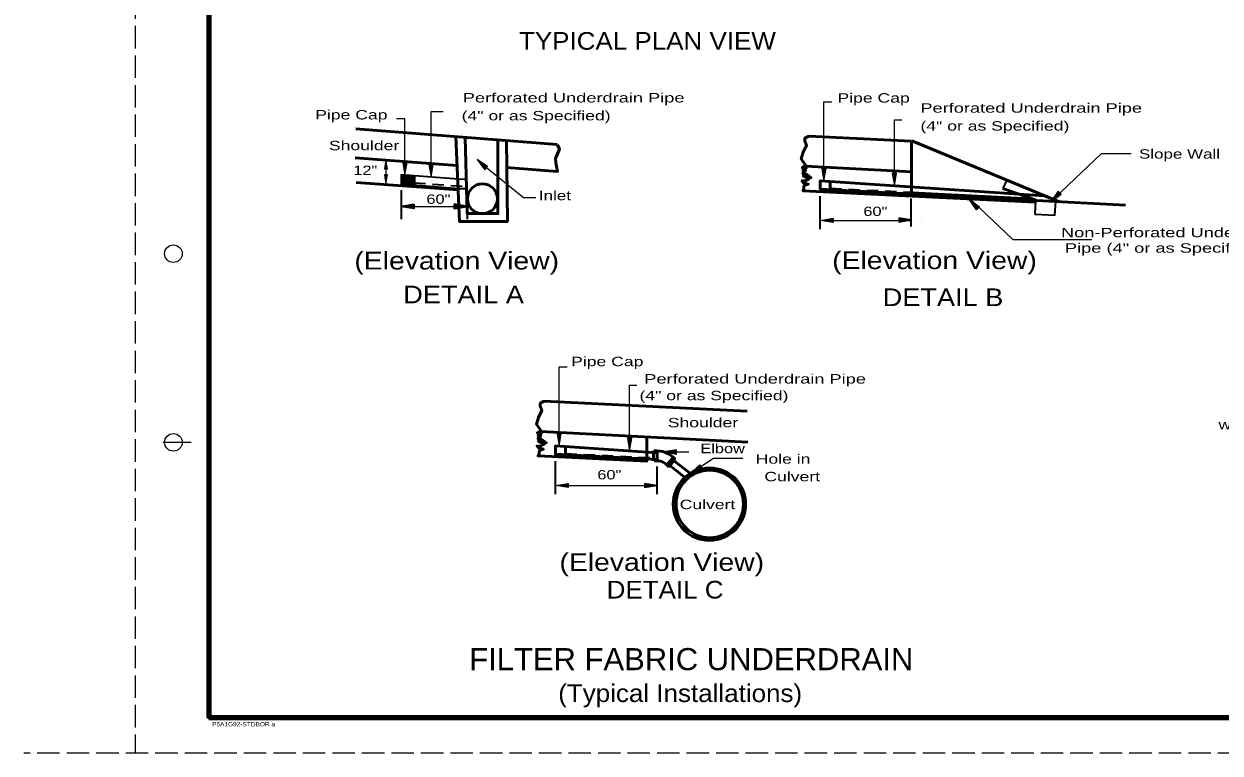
# Model space of a CAD drawing. Extents: x 36 to 71.3, y 0.3 to 22.3.
# Drawn here: x 35.97 to 52.91, y 0.32 to 10.65 of the extents above; entities that cross this region are included whole.
import ezdxf

# ---------------------------------------------------------------- set-up
doc = ezdxf.new("R2010")
doc.units = 0
doc.header["$LTSCALE"] = 0.053
doc.header["$PDMODE"] = 32
doc.header["$PDSIZE"] = 0.0265
doc.linetypes.add('LONG_DASHED', pattern=[7.5, 6, -1.5])
doc.linetypes.add('MEDIUM_DASHED', pattern=[4.5, 3, -1.5])
for name, color, linetype, lineweight in [('1', 7, 'Continuous', 13), ('2', 7, 'Continuous', 13), ('3', 7, 'MEDIUM_DASHED', 53), ('4', 7, 'Continuous', 13)]:
    doc.layers.add(name, color=color, linetype=linetype, lineweight=lineweight)

msp = doc.modelspace()

# ---------------------------------------------------------------- hatches: boundary and pattern name
at = {"layer": '1'}
for points in [[(41.49425, 8.09608), (41.49425, 8.03608), (41.31425, 8.06608), (41.31425, 8.06608)], [(42.068, 8.09608), (42.068, 8.03608), (42.248, 8.06608), (42.248, 8.06608)], [(47.43092, 7.89775), (47.43092, 7.83775), (47.25092, 7.86775), (47.25092, 7.86775)], [(48.36508, 7.9035), (48.36508, 7.8435), (48.54508, 7.8735), (48.54508, 7.8735)], [(43.68133, 4.14325), (43.68133, 4.08325), (43.50133, 4.11325), (43.50133, 4.11325)], [(44.76017, 4.14325), (44.76017, 4.08325), (44.94017, 4.11325), (44.94017, 4.11325)]]:
    msp.add_hatch(color=256, dxfattribs=at).paths.add_polyline_path(points)
at = {"layer": '2'}
for points in [[(41.07933, 8.59492), (41.12133, 8.59492), (41.10033, 8.72092), (41.10033, 8.72092)], [(41.3985, 8.6875), (41.33842, 8.6875), (41.3685, 8.5075), (41.3685, 8.5075)], [(41.76967, 8.66058), (41.70967, 8.66058), (41.73967, 8.48058), (41.73967, 8.48058)], [(42.49842, 8.58508), (42.54008, 8.62817), (42.38983, 8.73167), (42.38983, 8.73167)], [(41.12067, 8.51042), (41.07858, 8.51042), (41.09967, 8.38442), (41.09967, 8.38442)], [(47.3325, 8.60425), (47.2725, 8.60425), (47.3025, 8.42425), (47.3025, 8.42425)], [(48.33058, 8.53792), (48.27058, 8.53792), (48.30058, 8.35792), (48.30058, 8.35792)], [(49.50558, 8.05942), (49.46217, 8.01792), (49.35958, 8.16892), (49.35958, 8.16892)], [(50.66292, 8.23942), (50.6195, 8.28092), (50.51692, 8.12992), (50.51692, 8.12992)], [(43.58292, 4.84975), (43.52292, 4.84975), (43.55292, 4.66975), (43.55292, 4.66975)], [(44.581, 4.78342), (44.521, 4.78342), (44.551, 4.60342), (44.551, 4.60342)], [(45.21667, 4.5575), (45.21667, 4.6175), (45.03667, 4.5875), (45.03667, 4.5875)], [(45.57683, 4.35783), (45.54383, 4.408), (45.40992, 4.28408), (45.40992, 4.28408)]]:
    msp.add_hatch(color=256, dxfattribs=at).paths.add_polyline_path(points)

# ---------------------------------------------------------------- linework, layer by layer
at = {"layer": '1', "linetype": 'LONG_DASHED', "lineweight": 25}
for p, q in [((37.54825, 22.32408), (37.54825, 0.32408)), ((71.17325, 0.32408), (35.97325, 0.32408))]:
    msp.add_line(p, q, dxfattribs=at)
at = {"layer": '1', "lineweight": 158}
msp.add_line((38.58992, 21.82408), (38.58992, 0.82408), dxfattribs=at)
at = {"layer": '1', "lineweight": 53}
for p, q in [((43.52525, 8.94167), (40.67283, 9.16183)), ((48.54408, 8.98942), (47.09092, 9.0615)), ((48.54408, 8.21133), (48.54408, 8.98433)), ((50.62542, 8.13375), (48.54675, 8.99183)), ((42.10342, 8.64642), (40.66417, 8.75333)), ((48.55392, 8.55517), (47.04233, 8.63392)), ((42.12075, 8.3015), (40.678, 8.40458)), ((47.393, 8.303), (47.393, 8.41625)), ((50.30617, 8.15142), (49.83617, 8.31967)), ((46.22508, 4.72667), (43.29275, 4.87942)), ((43.64342, 4.5485), (43.64342, 4.66175)), ((44.89, 4.60192), (44.89, 4.4645)), ((45.1035, 4.37542), (45.1955, 4.48617))]:
    msp.add_line(p, q, dxfattribs=at)
at = {"layer": '1'}
for p, q in [((41.34433, 8.50792), (41.3145, 8.48583)), ((41.3145, 8.42708), (41.40508, 8.503)), ((41.315, 8.46725), (41.36442, 8.50492)), ((41.315, 8.49708), (41.41583, 8.38008)), ((41.31542, 8.39425), (41.44475, 8.5005)), ((41.31592, 8.44808), (41.38792, 8.504)), ((41.31642, 8.41042), (41.42267, 8.502)), ((41.31642, 8.46967), (41.39375, 8.38058)), ((41.32275, 8.38542), (41.46725, 8.49908)), ((41.32725, 8.50842), (41.44475, 8.37667)), ((41.34342, 8.38542), (41.48833, 8.49758)), ((41.35617, 8.50592), (41.46925, 8.37517)), ((41.36933, 8.3835), (41.49867, 8.48533)), ((41.37958, 8.50492), (41.49417, 8.37317)), ((41.40017, 8.503), (41.50017, 8.383)), ((41.41833, 8.502), (41.50158, 8.406)), ((41.44675, 8.49958), (41.50058, 8.43592)), ((41.47317, 8.49858), (41.50208, 8.46325)), ((41.31592, 8.44958), (41.37425, 8.383)), ((41.31592, 8.42858), (41.35708, 8.38492)), ((41.31592, 8.41042), (41.33742, 8.38592)), ((41.39725, 8.38058), (41.49967, 8.46575)), ((41.41783, 8.37808), (41.50017, 8.44717)), ((41.43833, 8.37767), (41.50058, 8.42758)), ((41.46192, 8.37517), (41.50058, 8.406)), ((41.48933, 8.37275), (41.50017, 8.38542)), ((38.33992, 4.72408), (37.93992, 4.72408))]:
    msp.add_line(p, q, dxfattribs=at)
at = {"layer": '1', "lineweight": 35}
for p, q in [((41.50267, 8.48858), (41.50267, 8.37658)), ((49.88608, 8.43317), (49.83617, 8.31967)), ((41.31425, 8.29667), (41.31425, 7.88608)), ((47.25092, 7.74325), (47.25092, 8.212)), ((48.53658, 7.78233), (48.53658, 8.17633)), ((42.248, 8.00383), (42.248, 7.88608)), ((43.50133, 3.98875), (43.50133, 4.4575)), ((44.94017, 3.98875), (44.94017, 4.38275))]:
    msp.add_line(p, q, dxfattribs=at)
at = {"layer": '1', "lineweight": 25}
for p, q in [((41.49425, 8.06608), (42.068, 8.06608)), ((47.43092, 7.86775), (48.53983, 7.86775)), ((43.68133, 4.11325), (44.76017, 4.11325))]:
    msp.add_line(p, q, dxfattribs=at)
at = {"layer": '1', "lineweight": 158}
msp.add_lwpolyline([(71.08992, 21.82408), (71.08992, 0.82408), (38.58992, 0.82408)], dxfattribs=at)
at = {"layer": '1', "lineweight": 53}
for points in [[(42.0895, 9.04983), (42.13983, 7.85225), (42.82042, 7.85225), (42.80825, 9.00017)], [(42.21967, 9.04092), (42.25092, 7.96425), (42.68675, 7.96425), (42.68675, 9.01417)], [(47.09092, 9.0615), (47.03367, 9.03225), (47.03367, 8.99408), (47.05625, 8.92792), (47.00933, 8.83242), (46.98158, 8.73825), (47.04233, 8.64792), (46.9955, 8.61483), (47.05275, 8.60975), (47.00417, 8.57667), (47.04233, 8.57667), (47.00417, 8.53842), (47.00417, 8.5295), (47.04233, 8.5295), (47.07183, 8.51042), (47.11875, 8.47225), (47.00933, 8.49642), (47.09092, 8.45317), (47.07533, 8.44808), (47.03883, 8.42517), (46.99025, 8.42517), (47.00933, 8.401), (47.0805, 8.38192), (47.02325, 8.36283), (47.01975, 8.34375), (47.01975, 8.31575), (47.00417, 8.2865), (50.29583, 8.12583)], [(43.53042, 8.93783), (43.5565, 8.87417), (43.50267, 8.74442), (43.50792, 8.682), (43.53042, 8.56108), (42.80825, 8.61458)], [(51.57533, 8.08125), (47.25067, 8.31067), (47.25067, 8.42775), (50.42208, 8.21692)], [(46.21467, 5.1645), (43.34133, 5.307), (43.28408, 5.27775), (43.28408, 5.23958), (43.30667, 5.17342), (43.25975, 5.07792), (43.232, 4.98375), (43.29275, 4.89342), (43.24592, 4.86033), (43.30317, 4.85525), (43.25458, 4.82217), (43.29275, 4.82217), (43.25458, 4.78392), (43.25458, 4.775), (43.29275, 4.775), (43.32225, 4.75592), (43.36917, 4.71775), (43.25975, 4.74192), (43.34133, 4.69867), (43.32575, 4.69358), (43.28925, 4.67067), (43.24067, 4.67067), (43.25975, 4.6465), (43.33092, 4.62742), (43.27367, 4.60833), (43.27017, 4.58925), (43.27017, 4.56125), (43.25458, 4.532), (44.7945, 4.45683), (44.7945, 4.803)], [(44.94208, 4.58033), (44.94208, 4.47975), (43.50108, 4.55617), (43.50108, 4.67325), (44.93683, 4.57775)], [(45.43508, 4.26467), (45.14692, 4.48617), (45.08967, 4.42), (45.37608, 4.19467)]]:
    msp.add_lwpolyline(points, dxfattribs=at)
at = {"layer": '1', "lineweight": 35}
msp.add_lwpolyline([(42.12075, 8.45292), (41.31342, 8.5115), (41.31342, 8.3855), (42.12592, 8.31933)], dxfattribs=at)
for points in [[(50.28683, 7.95717), (50.57458, 7.94217), (50.58483, 8.13425), (50.29675, 8.14942)], [(41.49425, 8.09608), (41.49425, 8.03608), (41.31425, 8.06608), (41.31425, 8.06608)], [(42.068, 8.09608), (42.068, 8.03608), (42.248, 8.06608), (42.248, 8.06608)]]:
    msp.add_lwpolyline(points, close=True, dxfattribs=at)
at = {"layer": '1'}
for points in [[(47.43092, 7.89775), (47.43092, 7.83775), (47.25092, 7.86775), (47.25092, 7.86775)], [(48.36508, 7.9035), (48.36508, 7.8435), (48.54508, 7.8735), (48.54508, 7.8735)], [(43.68133, 4.14325), (43.68133, 4.08325), (43.50133, 4.11325), (43.50133, 4.11325)], [(44.76017, 4.14325), (44.76017, 4.08325), (44.94017, 4.11325), (44.94017, 4.11325)]]:
    msp.add_lwpolyline(points, close=True, dxfattribs=at)
at = {"layer": '1', "lineweight": 53}
for centre, radius in [((42.46708, 8.173), 0.21258), ((45.68075, 3.84858), 0.51289), ((45.68508, 3.85108), 0.47725)]:
    msp.add_circle(centre, radius, dxfattribs=at)
at = {"layer": '1'}
for centre in [(38.08992, 7.39575), (38.08992, 4.72408)]:
    msp.add_circle(centre, 0.125, dxfattribs=at)
at = {"layer": '1', "lineweight": 53}
for centre, radius, start, end in [((44.92942, 4.24708), 0.35686, 41.78259, 96.06632), ((44.93925, 4.2665), 0.19717, 32.66104, 101.88244)]:
    msp.add_arc(centre, radius, start, end, dxfattribs=at)
at = {"layer": '1'}
msp.add_point((38.58992, 0.82408), dxfattribs=at)
at = {"layer": '2', "lineweight": 25}
for p, q in [((41.10033, 8.72092), (41.10033, 8.37725)), ((49.97683, 7.596), (49.31467, 8.22283)), ((49.97683, 7.596), (51.0975, 7.596)), ((45.21667, 4.5875), (45.38892, 4.5875))]:
    msp.add_line(p, q, dxfattribs=at)
for points in [[(47.3025, 8.60425), (47.3025, 9.54808), (47.41417, 9.54808)], [(41.73967, 8.66058), (41.73967, 9.40767), (41.9115, 9.40767)], [(41.3685, 8.6875), (41.3685, 9.30583), (41.24817, 9.30583)], [(48.30058, 8.53792), (48.30058, 9.29058), (48.40433, 9.29058)], [(50.57092, 8.18633), (51.23308, 8.81317), (51.65125, 8.81317)], [(42.475, 8.65425), (43.04942, 8.18975), (43.22125, 8.18975)], [(43.55292, 4.84975), (43.55292, 5.79358), (43.66458, 5.79358)], [(44.551, 4.78342), (44.551, 5.53608), (44.65475, 5.53608)], [(45.56033, 4.38292), (45.7365, 4.49875), (46.15467, 4.49875)]]:
    msp.add_lwpolyline(points, dxfattribs=at)
at = {"layer": '2'}
for points in [[(41.07933, 8.59492), (41.12133, 8.59492), (41.10033, 8.72092), (41.10033, 8.72092)], [(41.3985, 8.6875), (41.33842, 8.6875), (41.3685, 8.5075), (41.3685, 8.5075)], [(41.76967, 8.66058), (41.70967, 8.66058), (41.73967, 8.48058), (41.73967, 8.48058)], [(42.49842, 8.58508), (42.54008, 8.62817), (42.38983, 8.73167), (42.38983, 8.73167)], [(41.12067, 8.51042), (41.07858, 8.51042), (41.09967, 8.38442), (41.09967, 8.38442)], [(47.3325, 8.60425), (47.2725, 8.60425), (47.3025, 8.42425), (47.3025, 8.42425)], [(48.33058, 8.53792), (48.27058, 8.53792), (48.30058, 8.35792), (48.30058, 8.35792)], [(49.50558, 8.05942), (49.46217, 8.01792), (49.35958, 8.16892), (49.35958, 8.16892)], [(50.66292, 8.23942), (50.6195, 8.28092), (50.51692, 8.12992), (50.51692, 8.12992)], [(43.58292, 4.84975), (43.52292, 4.84975), (43.55292, 4.66975), (43.55292, 4.66975)], [(44.581, 4.78342), (44.521, 4.78342), (44.551, 4.60342), (44.551, 4.60342)], [(45.21667, 4.5575), (45.21667, 4.6175), (45.03667, 4.5875), (45.03667, 4.5875)], [(45.57683, 4.35783), (45.54383, 4.408), (45.40992, 4.28408), (45.40992, 4.28408)]]:
    msp.add_lwpolyline(points, close=True, dxfattribs=at)
at = {"layer": '3', "lineweight": 35}
for p, q in [((41.50267, 8.3995), (42.23358, 8.34608)), ((42.23883, 8.444), (42.12075, 8.45292)), ((42.12592, 8.31933), (42.22842, 8.31933))]:
    msp.add_line(p, q, dxfattribs=at)
at = {"layer": '3'}
for p, q in [((47.393, 8.31192), (48.54742, 8.25558)), ((43.64342, 4.55742), (44.94033, 4.49375))]:
    msp.add_line(p, q, dxfattribs=at)
at = {"layer": '3', "linetype": 'Continuous'}
msp.add_line((48.54742, 8.2555), (50.23467, 8.17317), dxfattribs=at)
at = {"layer": '4', "lineweight": 35}
for p, q in [((41.31425, 8.35917), (41.31433, 8.35917)), ((42.248, 8.06633), (42.24808, 8.06633)), ((42.248, 8.06608), (42.24808, 8.06608))]:
    msp.add_line(p, q, dxfattribs=at)
at = {"layer": '4'}
for p, q in [((47.25092, 7.86775), (47.251, 7.86775)), ((48.68975, 7.86775), (48.68983, 7.86775)), ((48.68975, 7.836), (48.68983, 7.836)), ((43.50133, 4.11325), (43.50142, 4.11325)), ((44.94017, 4.11325), (44.94025, 4.11325)), ((44.94017, 4.0815), (44.94025, 4.0815))]:
    msp.add_line(p, q, dxfattribs=at)

# ---------------------------------------------------------------- texts
at = {"layer": '1', "width": 1.15}
msp.add_text('P5A1G92-STDBOR a', height=0.06, dxfattribs=at).set_placement((38.63792, 0.70308))
at = {"layer": '2'}
for s, height, width, p in [('TYPICAL PLAN VIEW', 0.25, 1.1, (42.98425, 10.28367)), ('Perforated Underdrain Pipe', 0.133, 1.45, (42.18883, 9.53733)), ('Pipe Cap', 0.133, 1.4, (47.49392, 9.535)), ('Perforated Underdrain Pipe', 0.133, 1.45, (48.66833, 9.39217)), ('Pipe Cap', 0.133, 1.4, (40.09792, 9.29692)), ('(4" or as Specified)', 0.133, 1.4, (42.1725, 9.28375)), ('(4" or as Specified)', 0.133, 1.4, (48.66917, 9.1385)), ('Shoulder', 0.133, 1.4, (40.29225, 8.86108)), ('Slope Wall', 0.133, 1.35, (51.76425, 8.74133)), ('12"', 0.133, 1.3, (40.63767, 8.50958)), ('60"', 0.133, 1.3, (41.67308, 8.102)), ('Inlet', 0.133, 1.35, (43.26633, 8.15283)), ('60"', 0.133, 1.3, (47.861, 7.92883)), (' Non-Perforated Underdrain', 0.133, 1.45, (50.58817, 7.62842)), ('Pipe (4" or as Specified)', 0.133, 1.45, (50.71592, 7.40958)), ('(Elevation View)', 0.25, 1.2, (40.653, 7.172)), ('(Elevation View)', 0.25, 1.2, (47.41942, 7.17733)), ('DETAIL A', 0.25, 1.15, (41.34467, 6.69242)), ('DETAIL B', 0.25, 1.15, (48.13433, 6.65358)), ('Pipe Cap', 0.133, 1.4, (43.72217, 5.80267)), ('Perforated Underdrain Pipe', 0.133, 1.45, (44.7585, 5.557)), ('(4" or as Specified)', 0.133, 1.4, (44.69092, 5.32058)), ('Shoulder', 0.133, 1.4, (45.09117, 4.937)), ('when placed at', 0.133, 1.4, (52.88983, 4.908)), ('Elbow', 0.133, 1.3, (45.55333, 4.57092)), ('Hole in', 0.133, 1.4, (46.33642, 4.42183)), ('60"', 0.133, 1.3, (44.09383, 4.19933)), ('Culvert', 0.133, 1.4, (46.45883, 4.1725)), ('Culvert', 0.133, 1.4, (45.25942, 3.77825)), ('(Elevation View)', 0.25, 1.2, (43.55692, 2.90342)), ('DETAIL C', 0.25, 1.1, (44.22567, 2.51275)), ('FILTER FABRIC UNDERDRAIN', 0.3125, 1.05, (42.279, 1.498)), ('(Typical Installations)', 0.25, 1.1, (43.53983, 1.04675))]:
    msp.add_text(s, height=height, dxfattribs=dict(at, width=width)).set_placement(p)

doc.saveas('drawing.dxf')
